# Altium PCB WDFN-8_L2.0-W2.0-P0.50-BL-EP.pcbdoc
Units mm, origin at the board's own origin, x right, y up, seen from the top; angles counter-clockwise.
Board outline 14.9 x 15.32 mm, 2 copper layers (Top Layer, Bottom Layer), stack 0 mm thick; 1 components, 0 nets, 9 pads, 0 vias.
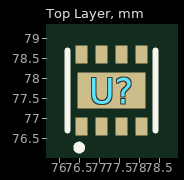
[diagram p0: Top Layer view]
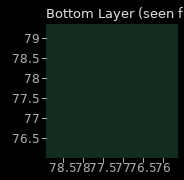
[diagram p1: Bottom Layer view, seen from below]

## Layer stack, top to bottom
Top Layer: signal copper (thickness not stored)
Bottom Layer: signal copper (thickness not stored)

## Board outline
84.75,69.85 69.85,69.85 69.85,85.169 84.75,85.169

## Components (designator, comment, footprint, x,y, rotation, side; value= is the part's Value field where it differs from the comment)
U? "" WDFN-8_L2.0-W2.0-P0.50-BL-EP 77.3,77.694 r0 top

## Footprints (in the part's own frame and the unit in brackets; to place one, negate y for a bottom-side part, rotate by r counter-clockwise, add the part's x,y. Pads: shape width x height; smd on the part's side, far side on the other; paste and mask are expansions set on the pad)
WDFN-8_L2.0-W2.0-P0.50-BL-EP [mm]
  rect 0.3x0.45 smd: 1(-0.75,-0.9) 2(-0.25,-0.9) 3(0.25,-0.9) 4(0.75,-0.9) 5(0.75,0.9) 6(0.25,0.9) 7(-0.25,0.9) 8(-0.75,0.9)
  rect 1.7x0.9 smd: 9(-0.002,-0.001)
  silkscreen extent -1.1,-1.49 1.1,1

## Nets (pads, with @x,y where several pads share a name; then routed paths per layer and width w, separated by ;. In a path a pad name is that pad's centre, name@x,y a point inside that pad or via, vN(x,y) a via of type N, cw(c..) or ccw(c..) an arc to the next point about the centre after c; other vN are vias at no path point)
pads on no net: U?.1 U?.2 U?.3 U?.4 U?.5 U?.6 U?.7 U?.8 U?.9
